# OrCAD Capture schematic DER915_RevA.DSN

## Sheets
1 PAGE1: size C
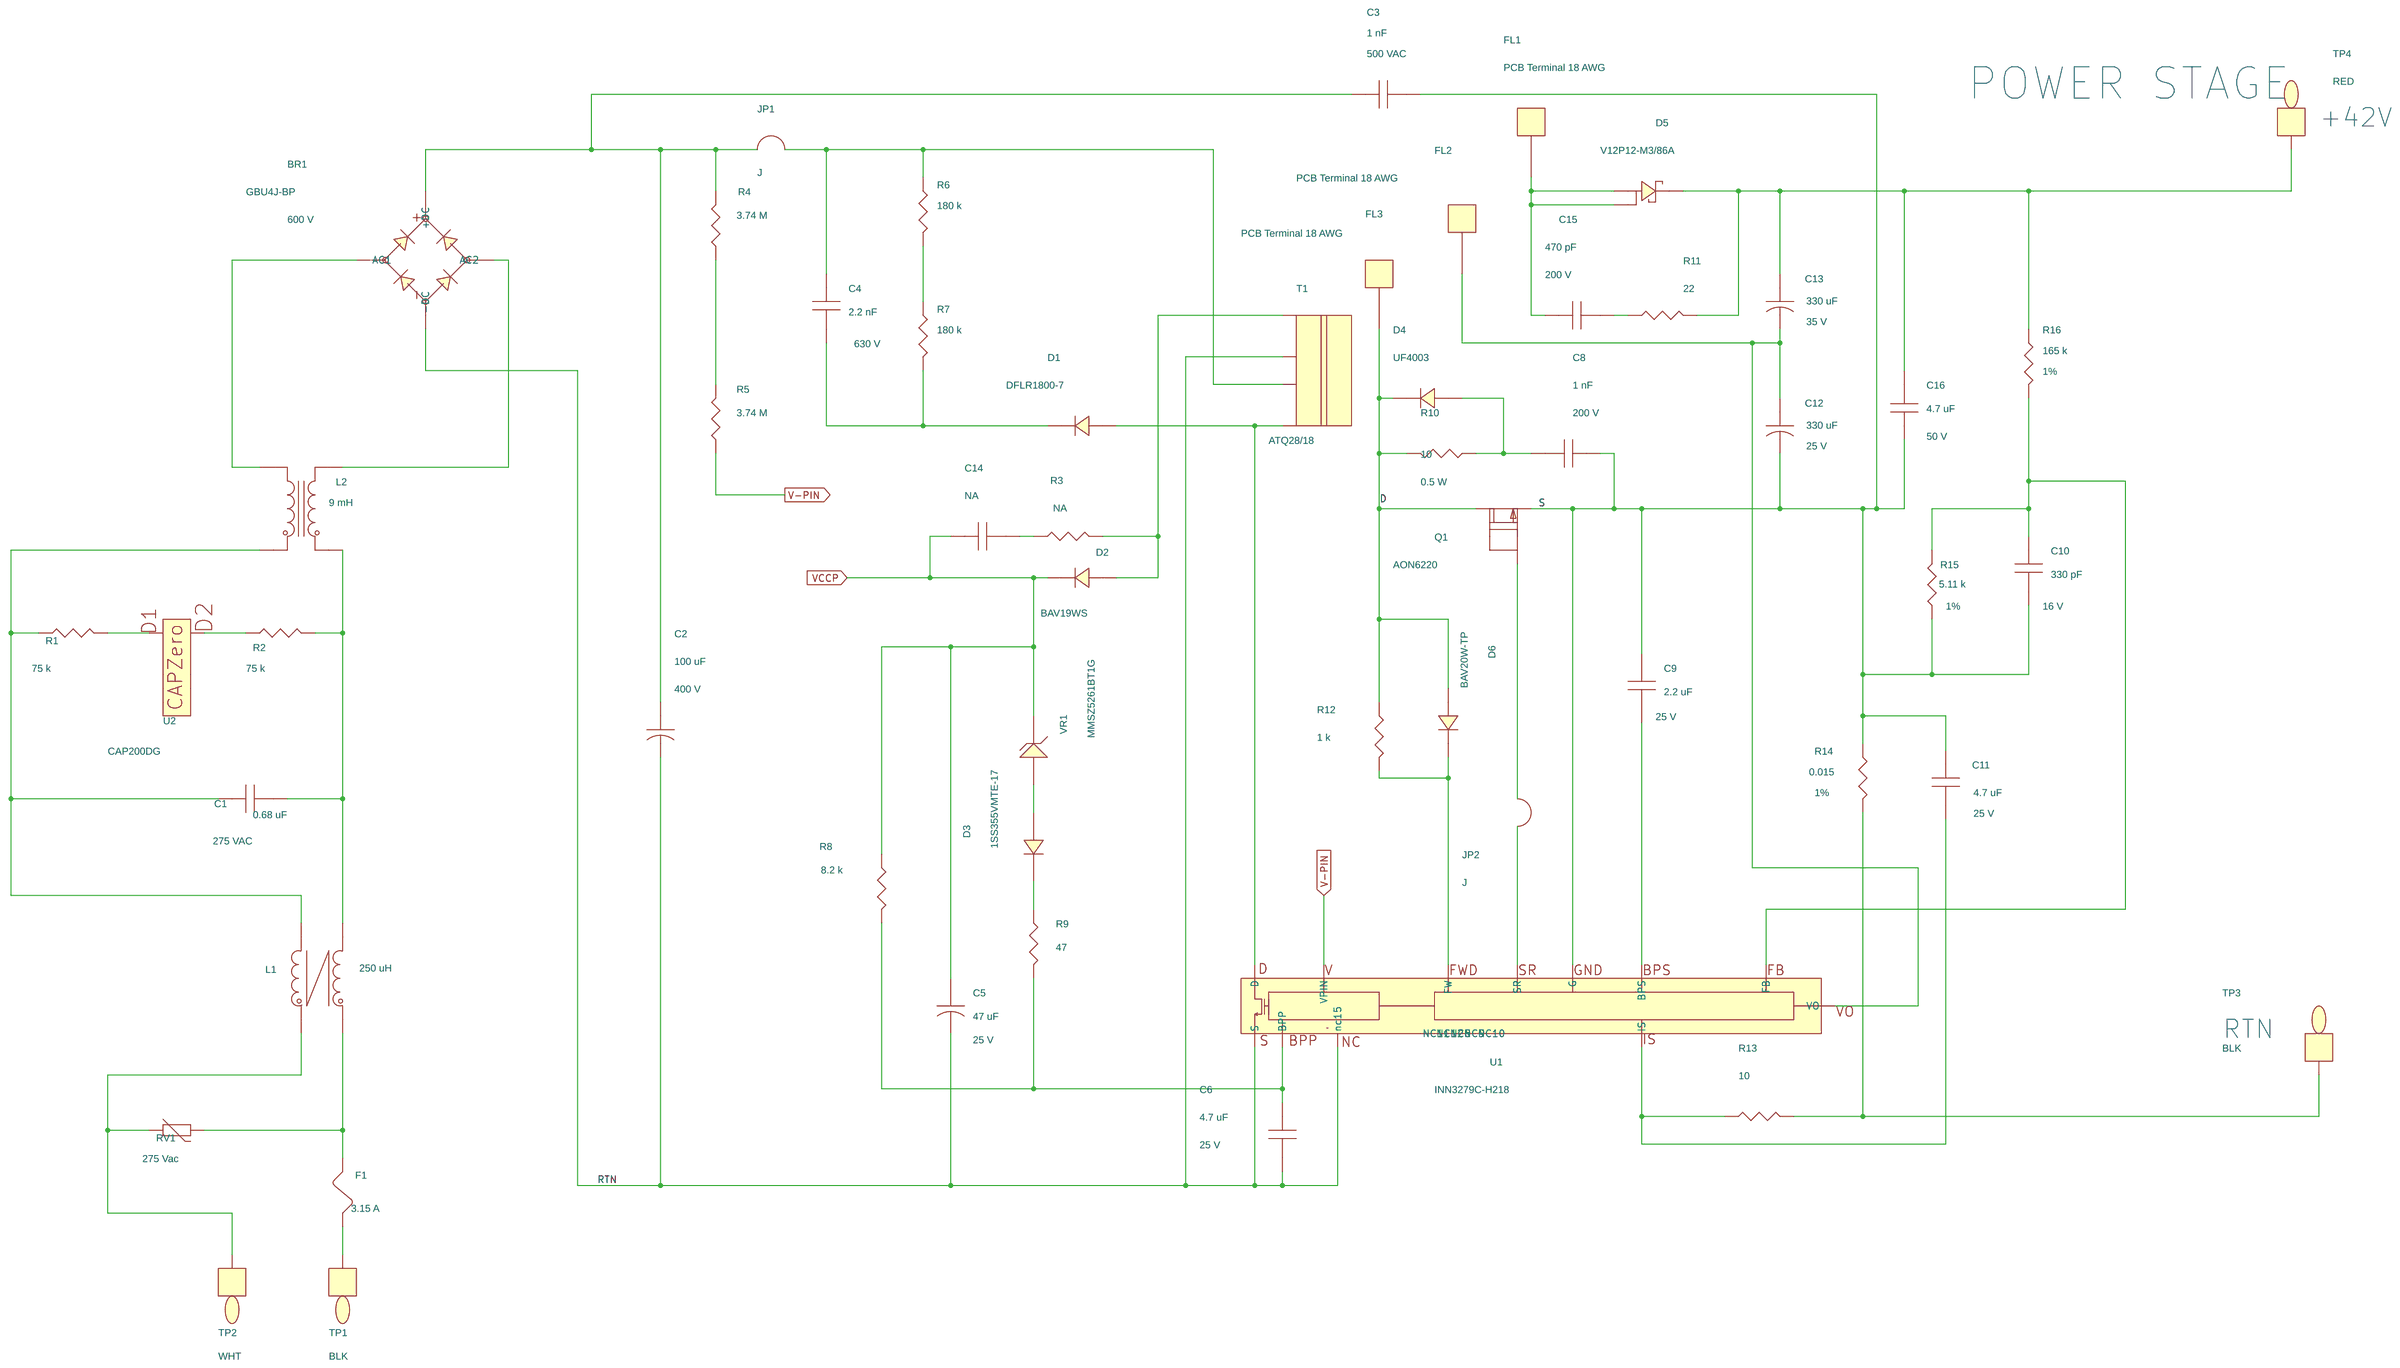
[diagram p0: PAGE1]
2 PAGE2

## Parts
BR1  GBU4J-BP  [pidaxbridgegbu8]
C1  0.68 uF  [pi_npcap18x10x16p1D40]
C2  100 uF  [pipolcapclyd710ls300040]
C3  1 nF  [pi_np475x200ls395d040]
C4  2.2 nF  [pismc1206]
C5  47 uF  [pipolcapclyd200ls80030]
C6  4.7 uF  [pismc0805]
C8  1 nF  [pismc0805]
C9  2.2 uF  [pismc0805]
C10  330 pF  [pismr0402]
C11  4.7 uF  [pismc0805]
C12  330 uF  [pipolcapcyld315ls138d030]
C13  330 uF  [pipolcapcyld400ls200040]
C14  NA  [pismc0805]
C15  470 pF  [pismc0805]
C16  4.7 uF  [pismc1206]
D1  DFLR1800-7  [pismddflr120012]
D2  BAV19WS  [pismsod323]
D3  1SS355VMTE-17  [pismdsod52312]
D4  UF4003  [pidv200x110x040do41]
D5  V12P12-M3/86A  [pi_sm_d_to-277a]
D6  BAV20W-TP  [pi_sm_sod-123_12]
F1  3.15 A  [pi_rst_microfuse]
FL1  PCB Terminal 18 AWG  [pi_hole_18awg]
FL2  PCB Terminal 18 AWG  [pi_hole_18awg]
FL3  PCB Terminal 18 AWG  [pi_hole_18awg]
JP1  J  [pi_jumper700]
JP2  J  [pi_jumper500_d020]
L1  250 uH  [pi_toroid_CMC4p_V_275uH]
L2  9 mH  [piind4p827x433ls315x354031]
Q1  AON6220  [pismpqfn5x6b]
R1  75 k  [pismr1206]
R2  75 k  [pismr1206]
R3  NA  [pismr0805]
R4  3.74 M  [pismr1206]
R5  3.74 M  [pismr1206]
R6  180 k  [pismr1206]
R7  180 k  [pismr1206]
R8  8.2 k  [pismr0603]
R9  47  [pismr0603]
R10  10  [pi12wvresd180ls150d040]
R11  22  [pismr1206]
R12  1 k  [pismr0603]
R13  10  [pismr0402]
R14  0.015  [pismr0805]
R15  5.11 k  [pismr0603]
R16  165 k  [pismr0603]
RV1  275 Vac  [pidisc500x225ls335x140040]
T1  ATQ28/18  [pi_bobbin_ATQ28_V_4P]
TP1  BLK  [pitpkeystone125x125]
TP2  WHT  [pitpkeystone125x125]
TP3  BLK  [pitpkeystone125x125]
TP4  RED  [pitpkeystone125x125]
U1  INN3279C-H218  [pi_ic_insop_24d]
U2  CAP200DG  [pi_ic_smd_so8_capzero]
VR1  MMSZ5261BT1G  [pi_sm_sod-123_12]

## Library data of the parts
BR1 = DISCRETE_BRIDGE_+~~-: Disp_Voltage: 600 V; Part Number: 15-00721-00
C1 = CAP_NP: ALT_SYMBOLS: pi_npcap18x10x16p1D40H; Disp_Voltage: 275 VAC; FPLIST: pi_npcap18x10x16p1D40,pi_npcap18x10x16p1D40H; Part Number: 20-01496-00; Voltage: 275 VAC
C2 = CAP_POL: ALT_SYMBOLS: pi_cap_cly_d710_ls300_040_1000h; COMPGROUP: 1; Disp_Voltage: 400 V; FPLIST: pipolcapclyd710ls300040,pi_cap_cly_d710_ls300_040_1000h; Part Number: 20-00832-00; Voltage: 400 V
C3 = CAP_NP: COMPGROUP: 3; Disp_Voltage: 500 VAC; PCB Editor PCBFP: pinpycaprad540x290ls400040; Part Number: 20-01061-00; Voltage: 500 VAC
C4 = CAP_NP: Disp_Voltage: 630 V; Part Number: 20-08609-00; Voltage: 630 V
C5 = CAP_POL: Disp_Voltage: 25 V; Part Number: 20-00094-00; Voltage: 25 V
C6 C11 = CAP_NP: Disp_Voltage: 25 V; Part Number: 20-09022-00; Voltage: 25 V
C8 C14 = CAP_NP: ALT_SYMBOLS: pismc0805_1; Disp_Voltage: 200 V; FPLIST: pismc0805,pismc0805_1; PCB Editor PCBFP: pismc0603; Part Number: 20-00737-00; Voltage: 200 V
C9 = CAP_NP: Disp_Voltage: 25 V; Part Number: 20-08603-00; Voltage: 25 V
C10 = CAP_NP: ALT_SYMBOLS: pismr0402_1; Disp_Voltage: 16 V; FPLIST: pismr0402,pismr0402_1; Part Number: 20-08910-00; Voltage: 16 V
C12 = CAP_POL: ALT_SYMBOLS: pipolcapcyld315ls138d030h; Disp_Voltage: 25 V; FPLIST: pipolcapcyld315ls138d030,pipolcapcyld315ls138d030h; Part Number: 20-09107-00; Voltage: 25 V
C13 = CAP_POL: Disp_Voltage: 35 V; Part Number: 20-01364-00; Voltage: 35 V
C15 = CAP_NP: Disp_Voltage: 200 V; Part Number: 20-01187-00; Voltage: 200 V
C16 = CAP_NP: Disp_Voltage: 50 V; Part Number: 20-08752-00; Voltage: 50 V
D1 = DIODE: COMPGROUP: 2; Part Number: 15-00919-00
D2 = DIODE: COMPGROUP: 1; Part Number: 15-00658-00
D3 = DIODE: Part Number: 15-01021-00; ROOM: 1
D4 = DIODE: ALT_SYMBOLS: pidax475x125040do41,pidv200x110x040do41wbead,pidax390x125040do41,pidax900x125040do41; FPLIST: pidv200x110x040do41,pidax475x125040do41,pidv200x110x040do41wbead,pidax390x125040do41,pidax900x125040do41; Part Number: 15-00107-00
D5 = DIODE_SCHOTTKY_TO-277A: Part Number: 15-01194-00
D6 = DIODE: Part Number: 15-01109-00
F1 = FUSE: ALT_SYMBOLS: pirstmicrofusehoz; COMPGROUP: 1; FPLIST: pi_rst_microfuse,pirstmicrofusehoz; Part Number: 40-00020-00
FL1-FL3 = TERM_1Pin: Part Number: 35-00007-00
JP1 = JUMPER_1: Part Number: 65-00046-00
JP2 = JUMPER_1: Part Number: 65-00600-03
L1 = TORRID_4P_12_34: ALT_SYMBOLS: pi_toroid_CMC4p_V,pi_toroid_CMC4p_V_275uH; FPLIST: pi_toroid_CMC4p_H,pi_toroid_CMC4p_V,pi_toroid_CMC4p_V_275uH; Part Number: 32-00367-00
L2 = INDUCTOR_4P_revG: Part Number: 30-00402-00
Q1 = FET_N_SGD_123_4_5678: Part Number: 50-00276-00
R1 R2 = R: Part Number: 05-01397-00
R3 = R: Part Number: 05-01591-00
R4 R5 = R: Part Number: 05-05572-00
R6 R7 = R: Part Number: 05-01406-00
R8 = R: Part Number: 05-01710-00
R9 = R: Part Number: 05-01656-00; ROOM: 2
R10 = R: ALT_SYMBOLS: pi12wvresd180ls200d040,pi12wvresd180ls250d040,pi12wresd180ls675d040; Disp_Power: 0.5 W; FPLIST: pi12wvresd180ls150d040,pi12wvresd180ls200d040,pi12wvresd180ls250d040,pi12wresd180ls675d040; Part Number: 05-02627-00
R11 = R: Part Number: 05-01312-00
R12 = R: Part Number: 05-01688-00
R13 = R: ALT_SYMBOLS: pismr0402_1; FPLIST: pismr0402,pismr0402_1; Part Number: 05-03538-00
R14 = R: Disp_Tol: 1%; Part Number: 05-06373-00
R15 = R: Disp_Tol: 1%; Part Number: 05-01146-00
R16 = R: Disp_Tol: 1%; Part Number: 05-01195-00
RV1 = VARISTOR: ALT_SYMBOLS: pirad550x410ls300040_h; FPLIST: pidisc500x225ls335x140040,pirad550x410ls300040_h; Part Number: 85-00011-00
T1 = BATQ28_4P_GENERIC: Part Number: 25-01170-00
TP1 TP3 = TESTPOINT: Part Number: 35-00042-00
TP2 = TESTPOINT: Part Number: 35-00044-00
TP4 = TESTPOINT: Part Number: 35-00043-00
U1 = Inno3CP_P15: Part Number: 10-01044-09
U2 = CAPZero: Part Number: 10-00958-00
VR1 = DIODE_ZENER: Part Number: 15-01102-00

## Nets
VCCP: C5.1 C14.1 D2.1 R8.1 VR1.1
D: D4.1 D6.2 FL3.1 Q1.5(D) R10.1 R12.1
NC8: U1.8(NC8)
NC9: U1.9(NC9)
NC10: U1.10(NC10)
NC11: U1.11(NC11)
NC12: U1.12(NC12)
RTN: BR1.4(-DC) C2.2 C5.2 C6.2 T1.2 U1.15(nc15) U1.16(S)
S: C3.2 C8.1 C9.1 C10.2 C11.1 C12.2 C16.1 Q1.1(S) R14.1 R15.1 U1.2(G)
V-PIN: R5.1 U1.13(VPIN)
N11472291: BR1.1(+DC) C2.1 C3.1 JP1.1 R4.2
N11472353: C4.1 JP1.2 R6.1 T1.3
N11472557: R4.1 R5.2
N11472561: C4.2 D1.1 R7.2
N11472629: C13.1 C16.2 D5.3(Cathode) R11.2 R16.1 TP4.1
N11472973: C10.1 R15.2 R16.2 U1.3(FB)
N11473077: C8.2 D4.2 R10.2
N11473461: D2.2 R3.1 T1.1
N11473531: C9.2 U1.4(BPS)
N11473833: D6.1 R12.2 U1.7(FW)
N11473887: R13.2 R14.2 TP3.1
N11473895: C11.2 R13.1 U1.1(IS)
N11474105: C6.1 R8.2 R9.2 U1.14(BPP)
N11474149: C1.1 L1.4 L2.1 R1.1
N11474707: C1.2 L1.2 L2.2 R2.2
N11475097: L1.3 RV1.1 TP2.1
N11475357: F1.2 L1.1 RV1.2
N11567485: R1.2 U2.2(D1)
N11567493: R2.1 U2.7(D2)
N11571354: D3.1 R9.1
N11586711: BR1.2(AC1) L2.4
N11586715: BR1.3(AC2) L2.3
N11591526: C14.2 R3.2
N11628013: C12.1 C13.2 FL2.1 U1.6(VO)
N11637010: C15.1 D5.1(A1) D5.2(A2) FL1.1
N11640393: D1.2 T1.4 U1.24(D)
N11675586: C15.2 R11.1
N11683724: F1.1 TP1.1
N11696107: JP2.1 Q1.4(G)
N11696111: JP2.2 U1.5(SR)
N11700020: R6.2 R7.1
N11712233: D3.2 VR1.2

Not connected (* = marked no-connect by the designer): Q1 2(S2) 3(S3) 6(D6) 7(D7) 8(D8); U2 1(NC1) 3(NC2) 4(NC3) 5(NC4) 6(NC5) 8(NC8)

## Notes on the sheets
sheet 1
- POWER STAGE
- +42V
- RTN
